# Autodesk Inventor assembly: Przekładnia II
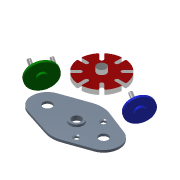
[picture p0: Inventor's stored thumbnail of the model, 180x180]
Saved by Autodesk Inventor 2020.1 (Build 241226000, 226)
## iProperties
Manager: www.cadconsulting.pl
Company: Fabian Stasiak CAD Consulting
Created: 2005-10
Part Number: Przekładnia II
Document SubType Name: Assembly
Designer: F.Stasiak
Author: F.Stasiak
Subject: Zbiór ćwiczeń. Autodesk Inventor 2020. Kurs podstawowy
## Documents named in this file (5)
- C:\2020_Kurs_podstawowy\R6 Zespoły\Kontakt\Przekładnia II.iam
- C:\2020_Kurs_podstawowy\R6 Zespoły\Kontakt\Płyta.ipt
- C:\2020_Kurs_podstawowy\R6 Zespoły\Kontakt\Koło1.ipt
- C:\2020_Kurs_podstawowy\R6 Zespoły\Kontakt\Koło2.ipt
- C:\2020_Kurs_podstawowy\R6 Zespoły\Kontakt\Koło3.ipt
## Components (4 placed, 4 different names)
1. Płyta:1
2. Koło1:1
3. Koło2:1
4. Koło3:1
